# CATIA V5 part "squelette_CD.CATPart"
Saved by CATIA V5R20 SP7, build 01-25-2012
Part number: squelette_CD
Publications: "C'", "barre_CD", "axe.pivot.D", "CC'", "axe.pivot.C", "Plan.pivot.C", "Plan.pivot.D"
Bounding box of the stored display mesh (mm): x -4.1 to 22.1, y -32 to -21, z 56.5 to 59
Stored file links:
  F:\IAO\Catia\squelette_CD.CATPart
  F:\IAO\Catia\squelette.CATProduct
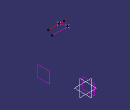
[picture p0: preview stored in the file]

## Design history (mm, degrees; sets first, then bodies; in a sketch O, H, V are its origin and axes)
Line1 "barre_CD": type PtPt, FirstPoint Point3, SecondPoint Point1, Support Plane1
Set1
  Plane1 "Plan.2,1": linked copy from another document
  Point1 "D": linked copy from another document
  Point2 "C": linked copy from another document
  Plane2 "plan.bati": linked copy from another document
Set2
  Point3 "C'": type OnPlane, Support Plane1, H -32, V 56.5, Direction (0, 1, 0)
  Line2 "axe.pivot.D": type Normal, RefPoint Point1, RefSkin Plane1, Start 0, End 20
  Line3 "CC'": type PtPt, FirstPoint Point3, SecondPoint Point2
  Line4 "axe.pivot.C": type Normal, RefPoint Point2, RefSkin Plane2, Start 0, End 20
  Plane3 "Plan.pivot.C": type Offset, RefPlane Plane2, Offset 0
  Plane4 "Plan.pivot.D": type Offset, RefPlane Plane1, Offset 0
Body1 (main body)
